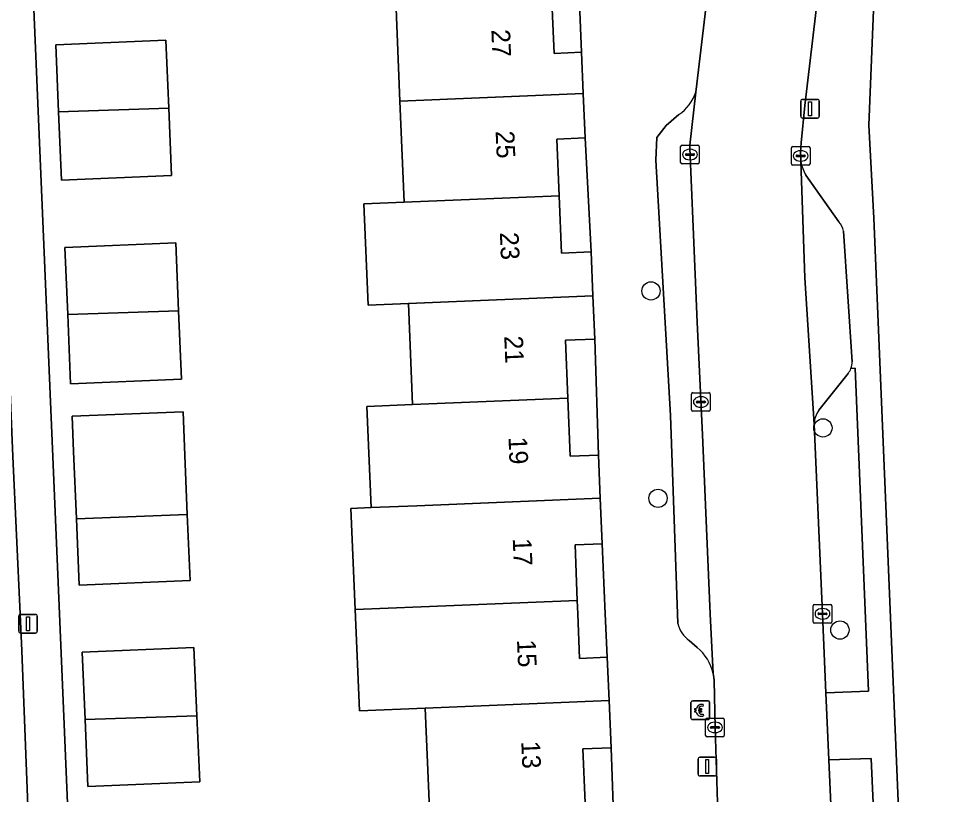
# Model space of a CAD drawing. Extents: x 161241 to 161758, y 384138 to 384885.
# Drawn here: x 161336.04 to 161385.2, y 384240.3 to 384281.92 of the extents above; entities that cross this region are included whole.
import ezdxf

# ---------------------------------------------------------------- set-up
doc = ezdxf.new("R2010")
doc.units = 0
for name, color, linetype in [('IMGEO_Betaalautomaat', 7, 'Continuous'), ('IMGEO_Boom', 7, 'Continuous'), ('IMGEO_Erf', 7, 'Continuous'), ('IMGEO_Groenvoorziening', 7, 'Continuous'), ('IMGEO_Kolk', 7, 'Continuous'), ('IMGEO_Lichtmast', 7, 'Continuous'), ('IMGEO_Pand', 7, 'Continuous'), ('IMGEO_Pand_nummerreeks', 7, 'Continuous'), ('IMGEO_Parkeervlak_open', 7, 'Continuous'), ('IMGEO_Rijbaan_lokaal_open', 7, 'Continuous'), ('IMGEO_Voetpad_open', 7, 'Continuous')]:
    doc.layers.add(name, color=color, linetype=linetype)

msp = doc.modelspace()

# ---------------------------------------------------------------- linework, layer by layer
at = {"layer": 'IMGEO_Betaalautomaat'}
for p, q in [((161372.161, 384245.326), (161373.002, 384245.326)), ((161373.002, 384245.326), (161372.161, 384245.326)), ((161372.086, 384244.402), (161372.086, 384245.243)), ((161372.086, 384245.243), (161372.086, 384244.402)), ((161372.369, 384244.79), (161372.369, 384244.858)), ((161372.49, 384244.858), (161372.49, 384244.79)), ((161372.748, 384245.131), (161372.731, 384245.031)), ((161373.085, 384245.252), (161373.085, 384244.411)), ((161373.085, 384244.411), (161373.085, 384245.252)), ((161373.011, 384244.327), (161372.17, 384244.327)), ((161372.17, 384244.327), (161373.011, 384244.327)), ((161372.735, 384244.625), (161372.757, 384244.538))]:
    msp.add_line(p, q, dxfattribs=at)
for points in [[(161372.369, 384244.858), (161372.3, 384244.858), (161372.3, 384244.927), (161372.379, 384244.927)], [(161372.374, 384244.721), (161372.3, 384244.721), (161372.3, 384244.79), (161372.369, 384244.79)], [(161372.501, 384244.927), (161372.648, 384244.927), (161372.648, 384244.858), (161372.49, 384244.858)], [(161372.49, 384244.79), (161372.648, 384244.79), (161372.648, 384244.721), (161372.504, 384244.721)]]:
    msp.add_lwpolyline(points, dxfattribs=at)
for centre, radius, start, end in [((161372.164, 384245.249), 0.0779, 92.4484, 184.2845), ((161372.164, 384245.249), 0.0779, 92.4484, 184.2845), ((161373.008, 384245.249), 0.0779, 2.4484, 94.2845), ((161373.008, 384245.249), 0.0779, 2.4484, 94.2845), ((161372.662, 384244.851), 0.293, 73.014, 165.0139), ((161372.668, 384244.864), 0.179, 69.3236, 159.5683), ((161372.164, 384244.405), 0.0779, 182.4484, 274.2845), ((161372.164, 384244.405), 0.0779, 182.4484, 274.2845), ((161372.635, 384244.776), 0.267, 191.8096, 297.0389), ((161372.668, 384244.791), 0.179, 202.7625, 291.8693), ((161373.008, 384244.405), 0.0779, 272.4484, 4.2845), ((161373.008, 384244.405), 0.0779, 272.4484, 4.2845)]:
    msp.add_arc(centre, radius, start, end, dxfattribs=at)
at = {"layer": 'IMGEO_Boom'}
for centre in [(161369.944, 384267.31), (161379.159, 384259.965), (161370.322, 384256.192), (161380.07, 384249.126)]:
    msp.add_circle(centre, 0.489, dxfattribs=at)
at = {"layer": 'IMGEO_Erf'}
for points in [[(161403.222, 384286.46), (161382.629, 384295.041), (161382.268, 384292.057), (161381.629, 384276.193), (161381.889, 384271.203), (161384.168, 384216.383), (161385.58, 384183.057), (161393.06, 384183.551), (161393.229, 384179.87), (161399.67, 384180.152), (161399.739, 384178.529), (161407.43, 384178.871), (161407.337, 384183.973), (161408.1, 384184.171), (161414.411, 384183.984), (161416.602, 384194.481), (161414.471, 384194.926), (161415.583, 384200.253), (161414.588, 384200.438), (161414.333, 384206.87)], [(161336.819, 384283.698), (161338.239, 384250), (161340.006, 384208.085)], [(161358.075, 384239.523), (161357.848, 384244.946), (161354.315, 384244.799), (161354.089, 384250.222), (161353.862, 384255.646), (161354.946, 384255.691), (161354.72, 384261.114), (161357.168, 384261.216), (161356.942, 384266.639), (161354.786, 384266.549), (161354.56, 384271.973), (161356.715, 384272.063), (161356.488, 384277.486), (161356.262, 384282.909)]]:
    msp.add_lwpolyline(points, dxfattribs=at)
for points in [[(161365.967, 384286.221), (161364.492, 384286.16), (161364.613, 384283.257), (161364.747, 384280.045), (161366.223, 384280.106)], [(161338.348, 384273.245), (161338.195, 384276.914), (161338.045, 384280.511), (161343.947, 384280.757), (161344.1, 384277.099), (161344.25, 384273.49)], [(161366.415, 384275.508), (161364.9, 384275.445), (161365.026, 384272.41), (161365.154, 384269.34), (161366.737, 384269.406)], [(161344.775, 384262.578), (161338.837, 384262.331), (161338.683, 384266.04), (161338.533, 384269.637), (161344.471, 384269.884), (161344.623, 384266.235)], [(161366.932, 384264.726), (161365.363, 384264.66), (161365.492, 384261.563), (161365.622, 384258.444), (161367.134, 384258.507)], [(161345.094, 384255.324), (161345.241, 384251.782), (161339.296, 384251.534), (161339.147, 384255.098), (161338.997, 384258.705), (161338.919, 384260.586), (161344.865, 384260.834), (161344.943, 384258.953)], [(161367.497, 384250), (161367.332, 384253.749), (161365.875, 384253.688), (161365.989, 384250.718), (161366.016, 384250), (161366.107, 384247.609), (161367.599, 384247.673)], [(161345.452, 384248.191), (161345.608, 384244.531), (161345.759, 384240.988), (161339.764, 384240.732), (161339.611, 384244.328), (161339.457, 384247.935)], [(161367.806, 384242.815), (161366.301, 384242.751), (161366.423, 384239.871), (161366.562, 384236.605), (161368.033, 384236.668)]]:
    msp.add_lwpolyline(points, close=True, dxfattribs=at)
at = {"layer": 'IMGEO_Groenvoorziening'}
for points in [[(161378.691, 384260.163), (161379.137, 384249.998), (161379.324, 384245.758), (161381.602, 384245.859), (161380.892, 384263.162)], [(161380.892, 384263.162), (161380.663, 384263.148)], [(161380.509, 384262.883), (161378.945, 384260.915)]]:
    msp.add_lwpolyline(points, dxfattribs=at)
msp.add_lwpolyline([(161379.483, 384242.162), (161380.186, 384226.202), (161380.635, 384226.221), (161382.002, 384226.279), (161382.455, 384226.302), (161381.747, 384242.244)], close=True, dxfattribs=at)
for centre, radius, start, end in [((161379.797, 384263.474), 0.925, 320.3061, 339.3694), ((161380.05, 384260.123), 1.359, 144.3632, 178.3103)]:
    msp.add_arc(centre, radius, start, end, dxfattribs=at)
at = {"layer": 'IMGEO_Kolk'}
for p, q in [((161371.534, 384274.195), (161371.534, 384275.047)), ((161371.609, 384275.121), (161372.461, 384275.121)), ((161372.022, 384274.901), (161372.047, 384274.901)), ((161372.535, 384275.047), (161372.535, 384274.195)), ((161377.47, 384274.122), (161377.47, 384274.974)), ((161377.545, 384275.048), (161378.397, 384275.048)), ((161377.958, 384274.828), (161377.983, 384274.828)), ((161378.471, 384274.974), (161378.471, 384274.122)), ((161371.793, 384274.615), (161371.793, 384274.627)), ((161372.231, 384274.578), (161371.833, 384274.578)), ((161371.836, 384274.664), (161372.234, 384274.664)), ((161372.045, 384274.341), (161372.02, 384274.341)), ((161372.277, 384274.627), (161372.277, 384274.615)), ((161377.729, 384274.542), (161377.729, 384274.554)), ((161378.167, 384274.505), (161377.769, 384274.505)), ((161377.772, 384274.591), (161378.17, 384274.591)), ((161377.981, 384274.268), (161377.956, 384274.268)), ((161378.213, 384274.554), (161378.213, 384274.542)), ((161372.461, 384274.121), (161371.609, 384274.121)), ((161378.397, 384274.048), (161377.545, 384274.048)), ((161372.118, 384260.928), (161372.118, 384261.78)), ((161372.193, 384261.854), (161373.045, 384261.854)), ((161372.606, 384261.634), (161372.631, 384261.634)), ((161373.119, 384261.78), (161373.119, 384260.928)), ((161372.377, 384261.348), (161372.377, 384261.36)), ((161372.815, 384261.311), (161372.417, 384261.311)), ((161372.42, 384261.397), (161372.818, 384261.397)), ((161372.629, 384261.074), (161372.604, 384261.074)), ((161372.861, 384261.36), (161372.861, 384261.348)), ((161373.045, 384260.854), (161372.193, 384260.854)), ((161378.636, 384249.572), (161378.636, 384250.424)), ((161378.711, 384250.498), (161379.563, 384250.498)), ((161379.124, 384250.278), (161379.149, 384250.278)), ((161379.637, 384250.424), (161379.637, 384249.572)), ((161378.895, 384249.992), (161378.895, 384250.004)), ((161379.333, 384249.955), (161378.935, 384249.955)), ((161378.938, 384250.041), (161379.336, 384250.041)), ((161379.147, 384249.718), (161379.122, 384249.718)), ((161379.379, 384250.004), (161379.379, 384249.992)), ((161379.563, 384249.498), (161378.711, 384249.498)), ((161372.873, 384243.48), (161372.873, 384244.332)), ((161372.948, 384244.406), (161373.8, 384244.406)), ((161373.874, 384244.332), (161373.874, 384243.48)), ((161373.132, 384243.9), (161373.132, 384243.912)), ((161373.57, 384243.863), (161373.172, 384243.863)), ((161373.175, 384243.949), (161373.573, 384243.949)), ((161373.361, 384244.186), (161373.386, 384244.186)), ((161373.616, 384243.912), (161373.616, 384243.9)), ((161373.8, 384243.406), (161372.948, 384243.406)), ((161373.384, 384243.626), (161373.359, 384243.626))]:
    msp.add_line(p, q, dxfattribs=at)
for points in [[(161371.534, 384274.195), (161371.534, 384275.047)], [(161371.609, 384275.121), (161372.461, 384275.121)], [(161372.535, 384275.047), (161372.535, 384274.195)], [(161377.47, 384274.122), (161377.47, 384274.974)], [(161377.545, 384275.048), (161378.397, 384275.048)], [(161378.471, 384274.974), (161378.471, 384274.122)], [(161372.461, 384274.121), (161371.609, 384274.121)], [(161378.397, 384274.048), (161377.545, 384274.048)], [(161372.118, 384260.928), (161372.118, 384261.78)], [(161372.193, 384261.854), (161373.045, 384261.854)], [(161373.119, 384261.78), (161373.119, 384260.928)], [(161373.045, 384260.854), (161372.193, 384260.854)], [(161378.636, 384249.572), (161378.636, 384250.424)], [(161378.711, 384250.498), (161379.563, 384250.498)], [(161379.637, 384250.424), (161379.637, 384249.572)], [(161379.563, 384249.498), (161378.711, 384249.498)], [(161372.873, 384243.48), (161372.873, 384244.332)], [(161372.948, 384244.406), (161373.8, 384244.406)], [(161373.874, 384244.332), (161373.874, 384243.48)], [(161373.8, 384243.406), (161372.948, 384243.406)]]:
    msp.add_lwpolyline(points, dxfattribs=at)
for centre, radius, start, end in [((161371.611, 384275.045), 0.0765, 91.552, 178.448), ((161371.611, 384275.045), 0.0765, 91.552, 178.448), ((161372.459, 384275.045), 0.0765, 1.552, 88.448), ((161372.459, 384275.045), 0.0765, 1.552, 88.448), ((161377.547, 384274.972), 0.0765, 91.552, 178.448), ((161377.547, 384274.972), 0.0765, 91.552, 178.448), ((161378.395, 384274.972), 0.0765, 1.552, 88.448), ((161378.395, 384274.972), 0.0765, 1.552, 88.448), ((161371.833, 384274.624), 0.0403, 85.8775, 175.7526), ((161371.83, 384274.614), 0.0366, 178.938, 274.7102), ((161372.234, 384274.621), 0.043, 264.8664, 352.4533), ((161372.238, 384274.626), 0.0386, 1.7309, 96.639), ((161377.769, 384274.551), 0.0403, 85.8775, 175.7526), ((161377.766, 384274.541), 0.0366, 178.938, 274.7102), ((161378.17, 384274.548), 0.043, 264.8664, 352.4533), ((161378.174, 384274.553), 0.0386, 1.7309, 96.639), ((161371.611, 384274.197), 0.0765, 181.552, 268.448), ((161371.611, 384274.197), 0.0765, 181.552, 268.448), ((161372.459, 384274.197), 0.0765, 271.552, 358.448), ((161372.459, 384274.197), 0.0765, 271.552, 358.448), ((161377.547, 384274.124), 0.0765, 181.552, 268.448), ((161377.547, 384274.124), 0.0765, 181.552, 268.448), ((161378.395, 384274.124), 0.0765, 271.552, 358.448), ((161378.395, 384274.124), 0.0765, 271.552, 358.448), ((161372.195, 384261.778), 0.0765, 91.552, 178.448), ((161372.195, 384261.778), 0.0765, 91.552, 178.448), ((161373.043, 384261.778), 0.0765, 1.552, 88.448), ((161373.043, 384261.778), 0.0765, 1.552, 88.448), ((161372.417, 384261.357), 0.0403, 85.8775, 175.7526), ((161372.414, 384261.347), 0.0366, 178.938, 274.7102), ((161372.818, 384261.354), 0.043, 264.8664, 352.4533), ((161372.822, 384261.359), 0.0386, 1.7309, 96.639), ((161372.195, 384260.93), 0.0765, 181.552, 268.448), ((161372.195, 384260.93), 0.0765, 181.552, 268.448), ((161373.043, 384260.93), 0.0765, 271.552, 358.448), ((161373.043, 384260.93), 0.0765, 271.552, 358.448), ((161378.713, 384250.422), 0.0765, 91.552, 178.448), ((161378.713, 384250.422), 0.0765, 91.552, 178.448), ((161379.561, 384250.422), 0.0765, 1.552, 88.448), ((161379.561, 384250.422), 0.0765, 1.552, 88.448), ((161378.935, 384250.001), 0.0403, 85.8775, 175.7526), ((161378.932, 384249.991), 0.0366, 178.938, 274.7102), ((161379.336, 384249.998), 0.043, 264.8664, 352.4533), ((161379.34, 384250.003), 0.0386, 1.7309, 96.639), ((161378.713, 384249.574), 0.0765, 181.552, 268.448), ((161378.713, 384249.574), 0.0765, 181.552, 268.448), ((161379.561, 384249.574), 0.0765, 271.552, 358.448), ((161379.561, 384249.574), 0.0765, 271.552, 358.448), ((161372.95, 384244.33), 0.0765, 91.552, 178.448), ((161372.95, 384244.33), 0.0765, 91.552, 178.448), ((161373.798, 384244.33), 0.0765, 1.552, 88.448), ((161373.798, 384244.33), 0.0765, 1.552, 88.448), ((161373.172, 384243.909), 0.0403, 85.8775, 175.7526), ((161373.169, 384243.899), 0.0366, 178.938, 274.7102), ((161373.573, 384243.906), 0.043, 264.8664, 352.4533), ((161373.577, 384243.911), 0.0386, 1.7309, 96.639), ((161372.95, 384243.482), 0.0765, 181.552, 268.448), ((161372.95, 384243.482), 0.0765, 181.552, 268.448), ((161373.798, 384243.482), 0.0765, 271.552, 358.448), ((161373.798, 384243.482), 0.0765, 271.552, 358.448)]:
    msp.add_arc(centre, radius, start, end, dxfattribs=at)
for centre, major_axis, ratio, start_param, end_param in [((161372.021, 384274.621), (-0.387, 0.002), 0.722429, 4.712389, 7.853982), ((161372.046, 384274.621), (-0.39, 0.002), 0.717154, 1.570796, 4.712389), ((161377.957, 384274.548), (-0.387, 0.002), 0.722429, 4.712389, 7.853982), ((161377.982, 384274.548), (-0.39, 0.002), 0.717154, 1.570796, 4.712389), ((161372.605, 384261.354), (-0.387, 0.002), 0.722429, 4.712389, 7.853982), ((161372.63, 384261.354), (-0.39, 0.002), 0.717154, 1.570796, 4.712389), ((161379.123, 384249.998), (-0.387, 0.002), 0.722429, 4.712389, 7.853982), ((161379.148, 384249.998), (-0.39, 0.002), 0.717154, 1.570796, 4.712389), ((161373.36, 384243.906), (-0.387, 0.002), 0.722429, 4.712389, 7.853982), ((161373.385, 384243.906), (-0.39, 0.002), 0.717154, 1.570796, 4.712389)]:
    msp.add_ellipse(centre, major_axis=major_axis, ratio=ratio, start_param=start_param, end_param=end_param, dxfattribs=at)
at = {"layer": 'IMGEO_Lichtmast'}
for p, q in [((161377.972, 384276.675), (161377.972, 384277.475)), ((161377.972, 384277.475), (161377.972, 384276.675)), ((161378.072, 384277.575), (161378.862, 384277.575)), ((161378.862, 384277.575), (161378.072, 384277.575)), ((161378.962, 384277.475), (161378.962, 384276.675)), ((161378.962, 384276.675), (161378.962, 384277.475)), ((161378.862, 384276.575), (161378.072, 384276.575)), ((161378.072, 384276.575), (161378.862, 384276.575)), ((161336.06, 384249.064), (161336.06, 384249.864)), ((161336.06, 384249.864), (161336.06, 384249.064)), ((161336.16, 384249.964), (161336.95, 384249.964)), ((161336.95, 384249.964), (161336.16, 384249.964)), ((161337.05, 384249.864), (161337.05, 384249.064)), ((161337.05, 384249.064), (161337.05, 384249.864)), ((161336.95, 384248.964), (161336.16, 384248.964)), ((161336.16, 384248.964), (161336.95, 384248.964)), ((161372.466, 384241.405), (161372.466, 384242.205)), ((161372.466, 384242.205), (161372.466, 384241.405)), ((161372.566, 384242.305), (161373.356, 384242.305)), ((161373.356, 384242.305), (161372.566, 384242.305)), ((161373.456, 384242.205), (161373.456, 384241.405)), ((161373.456, 384241.405), (161373.456, 384242.205)), ((161373.356, 384241.305), (161372.566, 384241.305)), ((161372.566, 384241.305), (161373.356, 384241.305))]:
    msp.add_line(p, q, dxfattribs=at)
for points in [[(161378.392, 384277.45), (161378.542, 384277.45), (161378.542, 384276.7), (161378.392, 384276.7), (161378.392, 384277.45)], [(161336.48, 384249.839), (161336.63, 384249.839), (161336.63, 384249.089), (161336.48, 384249.089), (161336.48, 384249.839)], [(161372.886, 384242.18), (161373.036, 384242.18), (161373.036, 384241.43), (161372.886, 384241.43), (161372.886, 384242.18)]]:
    msp.add_lwpolyline(points, dxfattribs=at)
for centre, start, end in [((161378.072, 384277.475), 90, 180), ((161378.072, 384277.475), 90, 180), ((161378.862, 384277.475), 0, 90), ((161378.862, 384277.475), 360, 90), ((161378.072, 384276.675), 180, 270), ((161378.072, 384276.675), 180, 270), ((161378.862, 384276.675), 270, 0), ((161378.862, 384276.675), 270, 0), ((161336.16, 384249.864), 90, 180), ((161336.16, 384249.864), 90, 180), ((161336.95, 384249.864), 0, 90), ((161336.95, 384249.864), 360, 90), ((161336.16, 384249.064), 180, 270), ((161336.16, 384249.064), 180, 270), ((161336.95, 384249.064), 270, 0), ((161336.95, 384249.064), 270, 0), ((161372.566, 384242.205), 90, 180), ((161372.566, 384242.205), 90, 180), ((161373.356, 384242.205), 0, 90), ((161373.356, 384242.205), 360, 90), ((161372.566, 384241.405), 180, 270), ((161372.566, 384241.405), 180, 270), ((161373.356, 384241.405), 270, 0), ((161373.356, 384241.405), 270, 0)]:
    msp.add_arc(centre, 0.1, start, end, dxfattribs=at)
at = {"layer": 'IMGEO_Pand'}
for points in [[(161366.223, 384280.106), (161364.747, 384280.045), (161364.613, 384283.257), (161356.262, 384282.909), (161356.488, 384277.486), (161366.315, 384277.896)], [(161344.1, 384277.099), (161343.947, 384280.757), (161338.045, 384280.511), (161338.195, 384276.914)], [(161366.315, 384277.896), (161356.488, 384277.486), (161356.715, 384272.063), (161365.026, 384272.41), (161364.9, 384275.445), (161366.415, 384275.508)], [(161338.195, 384276.914), (161338.348, 384273.245), (161344.25, 384273.49), (161344.1, 384277.099)], [(161365.026, 384272.41), (161356.715, 384272.063), (161354.56, 384271.973), (161354.786, 384266.549), (161356.942, 384266.639), (161366.835, 384267.052), (161366.737, 384269.406), (161365.154, 384269.34)], [(161344.623, 384266.235), (161344.471, 384269.884), (161338.533, 384269.637), (161338.683, 384266.04)], [(161366.835, 384267.052), (161356.942, 384266.639), (161357.168, 384261.216), (161365.492, 384261.563), (161365.363, 384264.66), (161366.932, 384264.726)], [(161338.683, 384266.04), (161338.837, 384262.331), (161344.775, 384262.578), (161344.623, 384266.235)], [(161365.492, 384261.563), (161357.168, 384261.216), (161354.72, 384261.114), (161354.946, 384255.691), (161357.395, 384255.793), (161367.23, 384256.203), (161367.134, 384258.507), (161365.622, 384258.444)], [(161344.943, 384258.953), (161344.865, 384260.834), (161338.919, 384260.586), (161338.997, 384258.705), (161339.147, 384255.098), (161345.094, 384255.324)], [(161365.875, 384253.688), (161367.332, 384253.749), (161367.23, 384256.203), (161357.395, 384255.793), (161354.946, 384255.691), (161353.862, 384255.646), (161354.089, 384250.222), (161357.622, 384250.369), (161365.989, 384250.718)], [(161339.147, 384255.098), (161339.296, 384251.534), (161345.241, 384251.782), (161345.094, 384255.324)], [(161366.016, 384250), (161365.989, 384250.718), (161357.622, 384250.369), (161354.089, 384250.222), (161354.315, 384244.799), (161357.848, 384244.946), (161367.698, 384245.357), (161367.599, 384247.673), (161366.107, 384247.609)], [(161345.608, 384244.531), (161345.452, 384248.191), (161339.457, 384247.935), (161339.611, 384244.328)], [(161367.698, 384245.357), (161357.848, 384244.946), (161358.075, 384239.523), (161366.423, 384239.871), (161366.301, 384242.751), (161367.806, 384242.815)], [(161339.611, 384244.328), (161339.764, 384240.732), (161345.759, 384240.988), (161345.608, 384244.531)]]:
    msp.add_lwpolyline(points, close=True, dxfattribs=at)
at = {"layer": 'IMGEO_Parkeervlak_open'}
for points in [[(161373.282, 384246.79), (161373.201, 384248.193), (161373.121, 384250), (161372.991, 384252.917), (161372.701, 384259.592), (161372.422, 384265.637), (161372.209, 384270.741), (161372.023, 384274.955), (161372.021, 384275.127), (161372.354, 384277.971)], [(161371.436, 384276.761), (161370.761, 384276.181), (161370.254, 384275.533), (161370.196, 384274.318), (161370.987, 384260.621), (161371.358, 384250), (161371.38, 384249.483)], [(161377.976, 384274.251), (161378.187, 384268.009), (161378.691, 384260.163)], [(161380.018, 384271.022), (161378.241, 384273.518)], [(161380.719, 384263.501), (161380.254, 384270.509)], [(161378.945, 384260.915), (161380.509, 384262.883)], [(161371.991, 384248.57), (161372.423, 384248.19)]]:
    msp.add_lwpolyline(points, dxfattribs=at)
for centre, radius, start, end in [((161370.038, 384278.775), 2.451, 304.7656, 340.8609), ((161380.238, 384274.654), 2.298, 190.1116, 209.6411), ((161379.375, 384270.415), 0.884, 6.0763, 43.3322), ((161379.832, 384263.461), 0.888, 339.3749, 2.5965), ((161379.797, 384263.474), 0.925, 320.3061, 339.3694), ((161380.05, 384260.123), 1.359, 144.3632, 178.3103), ((161372.942, 384249.868), 1.609, 193.8316, 233.7511), ((161370.804, 384246.233), 2.54, 12.6681, 50.396)]:
    msp.add_arc(centre, radius, start, end, dxfattribs=at)
at = {"layer": 'IMGEO_Rijbaan_lokaal_open'}
for points in [[(161373.201, 384285.193), (161372.354, 384277.971), (161372.021, 384275.127), (161372.023, 384274.955), (161372.209, 384270.741), (161372.422, 384265.637), (161372.701, 384259.592), (161372.991, 384252.917), (161373.121, 384250), (161373.201, 384248.193), (161373.282, 384246.79), (161373.313, 384246.58), (161373.336, 384246.428), (161373.376, 384243.89), (161373.501, 384239.874)], [(161380.186, 384226.202), (161379.483, 384242.162), (161379.324, 384245.758), (161379.137, 384249.998), (161378.691, 384260.163), (161378.187, 384268.009), (161377.976, 384274.251), (161377.968, 384274.518), (161377.967, 384274.752), (161377.986, 384275.243), (161378.196, 384277.255), (161379.046, 384284.508)], [(161336.684, 384236.002), (161336.225, 384248.01), (161336.134, 384250), (161335.741, 384258.44), (161335.543, 384263.223), (161335.328, 384268.908), (161335.107, 384273.512), (161334.887, 384278.846), (161333.256, 384278.821), (161331.584, 384278.687), (161331.739, 384274.994), (161331.985, 384270.03), (161332.284, 384263.343), (161332.501, 384257.819), (161332.832, 384250), (161332.915, 384248.051), (161333.147, 384242.867), (161333.411, 384236.512)]]:
    msp.add_lwpolyline(points, dxfattribs=at)
at = {"layer": 'IMGEO_Voetpad_open'}
for points in [[(161372.354, 384277.971), (161373.201, 384285.193), (161373.523, 384287.939), (161374.069, 384292.593), (161373.573, 384292.651), (161374.916, 384304.121), (161375.412, 384304.063), (161380.553, 384347.92), (161380.816, 384350.22), (161380.32, 384350.276), (161381.533, 384360.863), (161382.029, 384360.807), (161382.338, 384363.509), (161382.385, 384363.904), (161382.703, 384366.584)], [(161381.889, 384271.203), (161381.629, 384276.193), (161382.268, 384292.057), (161382.629, 384295.041), (161383.002, 384298.118), (161381.263, 384298.301), (161380.767, 384298.362), (161380.712, 384297.896), (161380.279, 384294.53), (161379.384, 384287.252), (161379.251, 384286.174), (161379.046, 384284.508), (161378.196, 384277.255), (161377.986, 384275.243), (161377.967, 384274.752), (161377.968, 384274.518), (161377.976, 384274.251)], [(161340.006, 384208.085), (161338.239, 384250), (161336.819, 384283.698), (161335.259, 384283.661), (161333.749, 384283.665), (161333.712, 384285.206), (161333.601, 384287.108), (161333.505, 384290.009), (161333.39, 384292.341), (161331.745, 384292.799), (161329.259, 384284.454), (161329.521, 384278.565), (161329.796, 384278.607), (161331.584, 384278.687), (161333.256, 384278.821), (161334.887, 384278.846), (161335.107, 384273.512), (161335.328, 384268.908), (161335.543, 384263.223), (161335.741, 384258.44), (161336.134, 384250), (161336.225, 384248.01), (161336.684, 384236.002)], [(161365.967, 384286.221), (161366.223, 384280.106), (161366.315, 384277.896), (161366.415, 384275.508), (161366.737, 384269.406), (161366.835, 384267.052), (161366.932, 384264.726), (161367.134, 384258.507), (161367.23, 384256.203), (161367.332, 384253.749), (161367.497, 384250), (161367.599, 384247.673), (161367.698, 384245.357), (161367.806, 384242.815), (161368.033, 384236.668)], [(161371.38, 384249.483), (161371.358, 384250), (161370.987, 384260.621), (161370.196, 384274.318), (161370.254, 384275.533), (161370.761, 384276.181), (161371.436, 384276.761)], [(161378.241, 384273.518), (161380.018, 384271.022)], [(161384.861, 384156.562), (161386.637, 384158.099), (161385.58, 384183.057), (161384.168, 384216.383), (161381.889, 384271.203)], [(161380.254, 384270.509), (161380.719, 384263.501)], [(161380.663, 384263.148), (161380.892, 384263.162), (161381.602, 384245.859), (161379.324, 384245.758), (161379.483, 384242.162), (161381.747, 384242.244), (161382.455, 384226.302)], [(161372.423, 384248.19), (161371.991, 384248.57)], [(161373.499, 384239.768), (161373.501, 384239.874), (161373.376, 384243.89), (161373.336, 384246.428), (161373.313, 384246.58), (161373.282, 384246.79)]]:
    msp.add_lwpolyline(points, dxfattribs=at)
for centre, radius, start, end in [((161370.038, 384278.775), 2.451, 304.7656, 340.8609), ((161380.238, 384274.654), 2.298, 190.1116, 209.6411), ((161379.375, 384270.415), 0.884, 6.0763, 43.3322), ((161379.832, 384263.461), 0.888, 339.3749, 2.5965), ((161372.942, 384249.868), 1.609, 193.8316, 233.7511), ((161370.804, 384246.233), 2.54, 12.6681, 50.396)]:
    msp.add_arc(centre, radius, start, end, dxfattribs=at)

# ---------------------------------------------------------------- texts
at = {"layer": 'IMGEO_Pand_nummerreeks'}
for s, rotation, p in [('27', 272.4061, (161361.389, 384281.316)), ('25', 272.4061, (161361.617, 384275.878)), ('23', 272.4062, (161361.845, 384270.44)), ('21', 272.4061, (161362.079, 384264.889)), ('19', 272.4062, (161362.306, 384259.473)), ('17', 272.4062, (161362.534, 384254.035)), ('15', 272.4062, (161362.763, 384248.597)), ('13', 272.4061, (161362.992, 384243.159))]:
    msp.add_text(s, height=1, rotation=rotation, dxfattribs=at).set_placement(p)

doc.saveas('drawing.dxf')
